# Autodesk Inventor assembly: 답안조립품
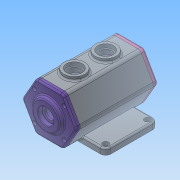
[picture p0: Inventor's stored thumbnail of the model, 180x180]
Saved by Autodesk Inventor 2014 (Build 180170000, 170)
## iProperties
Created: 2021-06
Part Number: 답안조립품
Document SubType Name: Assembly
Designer: net
Author: net
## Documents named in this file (4)
- C:\Users\net\Desktop\710606V1002\답안조립품.iam
- C:\Users\net\Desktop\710606V1002\답안부품.ipt
- C:\Users\net\Desktop\710606V1002\뒷커버.ipt
- C:\Users\net\Desktop\710606V1002\앞커버.ipt
